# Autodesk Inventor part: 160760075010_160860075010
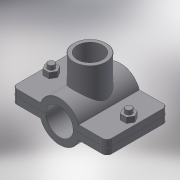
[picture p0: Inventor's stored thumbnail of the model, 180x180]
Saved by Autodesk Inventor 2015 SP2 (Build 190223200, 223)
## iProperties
Created: 2017-05
Part Number: 160760075010_160860075010
Material: Generic
Description: PLASSON SADDLE 75-1"
Document SubType Name: Modeling
Designer: KIM
Density: 1 g/cm^3
Appearance: Default
Author: KIM
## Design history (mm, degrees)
derived "16076.ipt"
feature "Solid1::16076.ipt"
feature "Solid2::16076.ipt"
tag "TaggingFeature1"
body "Solid1"
other parameters: "d0" = 93.75, "d1" = 122, "d2" = 37.5, "d3" = 75, "d4" = 98, "d5" = 0, "d6" = 6.1, "d7" = 122, "d8" = 0.1, "d10" = 0, "d11" = 0.75, "d14" = 39.3783, "d20" = 0.75, "d23" = 0.75, "d37" = 8, "d38" = 45.5, "d39" = 0, "d40" = 3, "d41" = 5, "d42" = 0, "d43" = 6, "d44" = 3, "d45" = 0, "d46" = 0.75, "d51" = 67, "d52" = 30.291, "d53" = 21, "d54" = 0, "d55" = 25, "d57" = 0, "d58" = 81, "d60" = 0, "d63" = 8, "d66" = 82, "d_" = 75, "B_" = 25, "G_" = 30.291, "A_" = 67, "L_" = 122, "L_1" = 98, "l_2" = 21
